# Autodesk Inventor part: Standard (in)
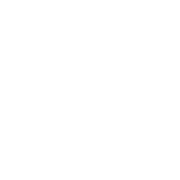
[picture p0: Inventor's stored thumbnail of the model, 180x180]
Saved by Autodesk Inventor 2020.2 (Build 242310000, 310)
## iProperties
Shininess: 64.0
Length Units: 11272
Angle Units: 11279
Time Units: 11290
Mass Units: 11286
Length Display Precision: 3
Angle Display Precision: 2
Compacted: True
Manager: www.cadconsulting.pl
Company: Fabian Stasiak CAD Consulting
Part Number: Standard (in)
Document SubType Name: Modeling
Created: 2002-08
Designer: F.Stasiak
Density: 1 g/cm^3
Material: Generic
Appearance: Default
Catalog Web Link: www.expertbooks.pl
Density: 0.0
Volumn: 0.0
Area: 0.0
PropertySet Name: Model Information
Control State: 0
Master: False
Checked Out: False
Author: F.Stasiak
Subject: Zbiór ćwiczeń. Autodesk Inventor 2020. Kurs Professional
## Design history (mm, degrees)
